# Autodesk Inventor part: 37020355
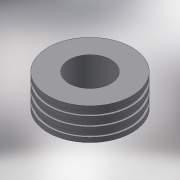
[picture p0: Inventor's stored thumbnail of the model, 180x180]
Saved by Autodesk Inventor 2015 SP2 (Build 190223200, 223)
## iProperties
Created: 2017-08
Part Number: 37020355
Material: Generic
Description: PLASSON MAN HOLE ADAPTOR 355
Document SubType Name: Modeling
Designer: Кирилл
Density: 1 g/cm^3
Appearance: Default
Author: Кирилл
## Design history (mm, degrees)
derived "37020-477207.ipt"
feature "Solid1::37020-477207.ipt"
tag "TaggingFeature1"
body "Solid1"
other parameters: "d0" = 135, "d2" = 475, "d3" = 313, "d4" = 355, "L_" = 135, "d_" = 355, "d_1" = 313
